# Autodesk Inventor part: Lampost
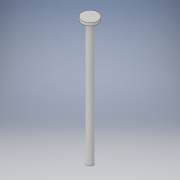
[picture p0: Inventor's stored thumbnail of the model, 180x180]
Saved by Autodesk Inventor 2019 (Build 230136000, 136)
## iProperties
Created: 2018-12
Part Number: Lampost
Material: Generic
Document SubType Name: Modeling
Designer: Patel Family
Density: 1 g/cm^3
Appearance: Default
Author: Patel Family
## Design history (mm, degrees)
sketch "Sketch1"
  geometry: C1 r 1 at (0, 0); 1 further point
  constraints: 1 centre point, 1 coincident
  dimensions: "d0" = 2 diameter of C1
extrude "Extrusion1" new body sketch "Sketch1" distance "d1" = 40; taper "d2" = 0 deg
sketch "Sketch2"
  geometry: C1 r 2.5 at (0, 0); 1 further point
  constraints: 1 centre point, 1 coincident
  dimensions: "d3" = 5 diameter of C1
extrude "Extrusion2" join sketch "Sketch2" distance "d4" = 0.9; taper "d5" = 0 deg
body "Solid1"
